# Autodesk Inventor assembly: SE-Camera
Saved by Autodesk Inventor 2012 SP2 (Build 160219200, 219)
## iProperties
Created: 2013-08
Part Number: SE-Camera
Document SubType Name: Assembly
Designer: hilarion
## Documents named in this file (8)
- L:\STI2D\Ressources eleves\ITEC\Tsti2d Fichot 2013-14\Webcam motorisee\SE-Camera.iam
- L:\STI2D\Ressources eleves\ITEC\Tsti2d Fichot 2013-14\Webcam motorisee\Demi-boitier avant.ipt
- L:\STI2D\Ressources eleves\ITEC\Tsti2d Fichot 2013-14\Webcam motorisee\Demi-boitier arriere.ipt
- L:\STI2D\Ressources eleves\ITEC\Tsti2d Fichot 2013-14\Webcam motorisee\Collerette.ipt
- L:\STI2D\Ressources eleves\ITEC\Tsti2d Fichot 2013-14\Webcam motorisee\Mini camera.ipt
- L:\STI2D\Ressources eleves\ITEC\Tsti2d Fichot 2013-14\Webcam motorisee\Carte electronique.ipt
- L:\STI2D\Ressources eleves\ITEC\Tsti2d Fichot 2013-14\Webcam motorisee\Moto-reducteur horizontal.ipt
- L:\STI2D\Ressources eleves\ITEC\Tsti2d Fichot 2013-14\Webcam motorisee\VisCBCrucFendueF1.ipt
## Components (10 placed, 7 different names)
1. Demi-boitier avant:1
2. Demi-boitier arriere:1
3. Collerette:1
4. Mini camera:1
5. Carte electronique:1
6. Moto-reducteur horizontal:1
7. VisCBCrucFendueF1:1
8. VisCBCrucFendueF1:2
9. VisCBCrucFendueF1:3
10. VisCBCrucFendueF1:4
